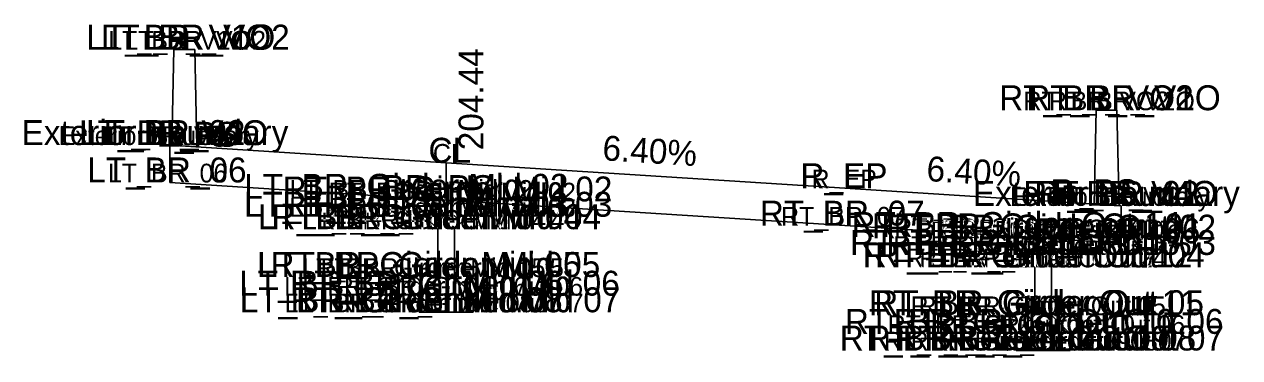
# Model space of a CAD drawing. Extents: x 1977765 to 1980293, y 795569 to 815181.
# Drawn here: x 1978023.5 to 1978072.25, y 807115.23 to 807128.6 of the extents above; entities that cross this region are included whole.
import ezdxf

# ---------------------------------------------------------------- set-up
doc = ezdxf.new("R2010")
doc.units = 0
for name, color, linetype in [('RD_Sketch5', 7, 'Continuous'), ('RD_XS_NewRW', 7, 'Continuous'), ('RD_XS_PaveOvlay', 7, 'Continuous'), ('RD_XS_TX_Elev_PR', 7, 'Continuous'), ('RD_XS_TX_Slope', 7, 'Continuous')]:
    doc.layers.add(name, color=color, linetype=linetype)

msp = doc.modelspace()

# ---------------------------------------------------------------- linework, layer by layer
at = {"layer": 'RD_XS_PaveOvlay'}
for points in [[(1978030.416, 807123.692), (1978030.332, 807127.589), (1978029.499, 807127.589), (1978029.416, 807123.756)], [(1978030.416, 807123.692), (1978030.332, 807127.589), (1978029.499, 807127.589), (1978029.416, 807123.756)], [(1978066.416, 807121.388), (1978066.499, 807125.157), (1978067.332, 807125.157), (1978067.416, 807121.324)], [(1978066.416, 807121.388), (1978066.499, 807125.157), (1978067.332, 807125.157), (1978067.416, 807121.324)], [(1978040.416, 807123.052), (1978029.332, 807123.761)], [(1978029.332, 807123.761), (1978029.332, 807122.261)], [(1978040.416, 807123.052), (1978029.332, 807123.761)], [(1978029.332, 807123.761), (1978029.332, 807122.261)], [(1978029.416, 807123.756), (1978030.416, 807123.692)], [(1978029.416, 807123.756), (1978030.416, 807123.692)], [(1978040.416, 807121.552), (1978040.416, 807123.052)], [(1978040.416, 807123.052), (1978056.416, 807122.028), (1978067.499, 807121.318)], [(1978040.416, 807121.552), (1978040.416, 807123.052)], [(1978040.416, 807121.552), (1978040.416, 807123.052)], [(1978040.416, 807123.052), (1978056.416, 807122.028), (1978067.499, 807121.318)], [(1978040.416, 807121.552), (1978040.416, 807123.052)], [(1978029.332, 807122.261), (1978040.416, 807121.552)], [(1978029.332, 807122.261), (1978040.416, 807121.552)], [(1978040.416, 807121.552), (1978039.582, 807121.605)], [(1978039.582, 807121.605), (1978039.582, 807120.885)], [(1978040.416, 807121.552), (1978039.582, 807121.605)], [(1978039.582, 807121.605), (1978039.582, 807120.885)], [(1978040.416, 807121.552), (1978041.249, 807121.498)], [(1978067.499, 807119.818), (1978056.416, 807120.528), (1978040.416, 807121.552)], [(1978040.416, 807121.552), (1978041.249, 807121.498)], [(1978067.499, 807119.818), (1978056.416, 807120.528), (1978040.416, 807121.552)], [(1978041.249, 807121.498), (1978041.249, 807120.885)], [(1978041.249, 807121.498), (1978041.249, 807120.885)], [(1978067.416, 807121.324), (1978066.416, 807121.388)], [(1978067.416, 807121.324), (1978066.416, 807121.388)], [(1978067.499, 807121.318), (1978067.499, 807119.818)], [(1978067.499, 807121.318), (1978067.499, 807119.818)], [(1978039.582, 807120.885), (1978040.082, 807120.385)], [(1978039.582, 807120.885), (1978040.082, 807120.385)], [(1978041.249, 807120.885), (1978040.749, 807120.385)], [(1978041.249, 807120.885), (1978040.749, 807120.385)], [(1978040.082, 807120.385), (1978040.082, 807118.468)], [(1978040.082, 807120.385), (1978040.082, 807118.468)], [(1978040.749, 807120.385), (1978040.749, 807118.468)], [(1978040.749, 807120.385), (1978040.749, 807118.468)], [(1978063.541, 807120.072), (1978064.374, 807120.018), (1978065.207, 807119.965)], [(1978063.541, 807119.352), (1978063.541, 807120.072)], [(1978063.541, 807120.072), (1978064.374, 807120.018), (1978065.207, 807119.965)], [(1978063.541, 807119.352), (1978063.541, 807120.072)], [(1978065.207, 807119.965), (1978065.207, 807119.352)], [(1978065.207, 807119.965), (1978065.207, 807119.352)], [(1978064.041, 807118.852), (1978063.541, 807119.352)], [(1978064.041, 807118.852), (1978063.541, 807119.352)], [(1978065.207, 807119.352), (1978064.707, 807118.852)], [(1978065.207, 807119.352), (1978064.707, 807118.852)], [(1978064.041, 807116.935), (1978064.041, 807118.852)], [(1978064.041, 807116.935), (1978064.041, 807118.852)], [(1978064.707, 807118.852), (1978064.707, 807116.935)], [(1978064.707, 807118.852), (1978064.707, 807116.935)], [(1978040.082, 807118.468), (1978039.332, 807117.718)], [(1978040.082, 807118.468), (1978039.332, 807117.718)], [(1978040.749, 807118.468), (1978041.499, 807117.718)], [(1978040.749, 807118.468), (1978041.499, 807117.718)], [(1978039.332, 807117.718), (1978039.332, 807117.052)], [(1978039.332, 807117.718), (1978039.332, 807117.052)], [(1978041.499, 807117.718), (1978041.499, 807117.052)], [(1978041.499, 807117.718), (1978041.499, 807117.052)], [(1978039.332, 807117.052), (1978040.416, 807117.052)], [(1978039.332, 807117.052), (1978040.416, 807117.052)], [(1978041.499, 807117.052), (1978040.416, 807117.052)], [(1978041.499, 807117.052), (1978040.416, 807117.052)], [(1978063.291, 807116.185), (1978064.041, 807116.935)], [(1978063.291, 807116.185), (1978064.041, 807116.935)], [(1978064.707, 807116.935), (1978065.457, 807116.185)], [(1978064.707, 807116.935), (1978065.457, 807116.185)], [(1978063.291, 807115.518), (1978063.291, 807116.185)], [(1978063.291, 807115.518), (1978063.291, 807116.185)], [(1978065.457, 807116.185), (1978065.457, 807115.518)], [(1978065.457, 807116.185), (1978065.457, 807115.518)], [(1978065.457, 807115.518), (1978064.374, 807115.518), (1978063.291, 807115.518)], [(1978065.457, 807115.518), (1978064.374, 807115.518), (1978063.291, 807115.518)]]:
    msp.add_lwpolyline(points, dxfattribs=at)

# ---------------------------------------------------------------- texts
at = {"layer": 'RD_Sketch5'}
for s, p in [('LT_BR_V1O', (1978025.983, 807127.589)), ('LT_BR_VO2', (1978026.565, 807127.589)), ('RT_BR_VO2', (1978062.605, 807125.157)), ('RT_BR_V1O', (1978063.691, 807125.157)), ('Exterior Boundary', (1978023.388, 807123.761)), ('LT_BR_V4O', (1978025.695, 807123.756)), ('LT_BR_02', (1978025.974, 807123.761)), ('L_PS', (1978028.798, 807123.692)), ('CL', (1978039.711, 807123.052)), ('LT_BR_06', (1978026.021, 807122.261)), ('R_EP', (1978054.632, 807122.028)), ('LT_BR_Girder Mid 02', (1978032.319, 807121.605)), ('RT_BR_Girder Mid 02', (1978033.859, 807121.498)), ('BR_PGL', (1978037.876, 807121.552)), ('R_PS', (1978064.672, 807121.388)), ('LT_BR_Girder Mid 03', (1978032.311, 807120.885)), ('RT_BR_Girder Mid 03', (1978033.851, 807120.885)), ('Exterior Boundary', (1978061.554, 807121.318)), ('RT_BR_V4O', (1978063.569, 807121.324)), ('RT_BR_02', (1978064.015, 807121.318)), ('LT_BR_Girder Mid 04', (1978032.866, 807120.385)), ('RT_BR_Girder Mid 04', (1978033.407, 807120.385)), ('RT_BR_07', (1978053.002, 807120.528)), ('RT_BR_Girder Out 14', (1978056.679, 807120.072)), ('RT_BR_Girder Out 01', (1978057.496, 807120.018)), ('RT_BR_Girder Out 02', (1978058.078, 807119.965)), ('RT_BR_06', (1978064.062, 807119.818)), ('RT_BR_Girder Out 13', (1978056.623, 807119.352)), ('RT_BR_Girder Out 03', (1978058.07, 807119.352)), ('LT_BR_Girder Mid 05', (1978032.834, 807118.468)), ('RT_BR_Girder Mid 05', (1978033.375, 807118.468)), ('RT_BR_Girder Out 12', (1978057.131, 807118.852)), ('RT_BR_Girder Out 04', (1978057.625, 807118.852)), ('LT_BR_Girder Mid 06', (1978032.116, 807117.718)), ('RT_BR_Girder Mid 06', (1978034.157, 807117.718)), ('LT_BR_Girder Mid 07', (1978032.14, 807117.052)), ('RT_BR_Girder Mid 07', (1978034.18, 807117.052)), ('BR_Girder Mid 08', (1978034.392, 807117.052)), ('RT_BR_Girder Out 11', (1978057.383, 807116.935)), ('RT_BR_Girder Out 05', (1978057.593, 807116.935)), ('RT_BR_Girder Out 10', (1978056.413, 807116.185)), ('RT_BR_Girder Out 06', (1978058.375, 807116.185)), ('RT_BR_Girder Out 09', (1978056.208, 807115.518)), ('RT_BR_Girder Out 08', (1978057.28, 807115.518)), ('RT_BR_Girder Out 07', (1978058.398, 807115.518))]:
    msp.add_text(s, height=1, dxfattribs=at).set_placement(p)
at = {"layer": 'RD_XS_NewRW'}
for s, p in [('LT_BR_V1O', (1978026.862, 807127.589)), ('LT_BR_VO2', (1978027.507, 807127.589)), ('RT_BR_VO2', (1978063.579, 807125.157)), ('RT_BR_V1O', (1978064.601, 807125.157)), ('Exterior Boundary', (1978024.874, 807123.761)), ('LT_BR_V4O', (1978026.625, 807123.756)), ('LT_BR_02', (1978026.814, 807123.761)), ('L_PS', (1978029.202, 807123.692)), ('CL', (1978039.887, 807123.052)), ('LT_BR_06', (1978026.849, 807122.261)), ('LT_BR_Girder Mid 02', (1978034.135, 807121.605)), ('R_EP', (1978055.078, 807122.028)), ('RT_BR_Girder Mid 02', (1978035.707, 807121.498)), ('BR_PGL', (1978038.511, 807121.552)), ('Exterior Boundary', (1978063.04, 807121.318)), ('RT_BR_V4O', (1978064.531, 807121.324)), ('RT_BR_02', (1978064.886, 807121.318)), ('R_PS', (1978065.108, 807121.388)), ('LT_BR_Girder Mid 03', (1978034.129, 807120.885)), ('RT_BR_Girder Mid 03', (1978035.701, 807120.885)), ('LT_BR_Girder Mid 04', (1978034.67, 807120.385)), ('RT_BR_Girder Mid 04', (1978035.242, 807120.385)), ('RT_BR_07', (1978053.856, 807120.528)), ('RT_BR_Girder Out 14', (1978058.394, 807120.072)), ('RT_BR_Girder Out 01', (1978059.216, 807120.018)), ('RT_BR_Girder Out 02', (1978059.86, 807119.965)), ('RT_BR_06', (1978064.921, 807119.818)), ('RT_BR_Girder Out 13', (1978058.353, 807119.352)), ('RT_BR_Girder Out 03', (1978059.854, 807119.352)), ('RT_BR_Girder Out 12', (1978058.859, 807118.852)), ('RT_BR_Girder Out 04', (1978059.395, 807118.852)), ('LT_BR_Girder Mid 05', (1978034.646, 807118.468)), ('RT_BR_Girder Mid 05', (1978035.219, 807118.468)), ('LT_BR_Girder Mid 06', (1978033.92, 807117.718)), ('RT_BR_Girder Mid 06', (1978035.992, 807117.718)), ('LT_BR_Girder Mid 07', (1978033.938, 807117.052)), ('BR_Girder Mid 08', (1978035.898, 807117.052)), ('RT_BR_Girder Mid 07', (1978036.01, 807117.052)), ('RT_BR_Girder Out 11', (1978059.048, 807116.935)), ('RT_BR_Girder Out 05', (1978059.372, 807116.935)), ('RT_BR_Girder Out 10', (1978058.132, 807116.185)), ('RT_BR_Girder Out 06', (1978060.145, 807116.185)), ('RT_BR_Girder Out 09', (1978057.979, 807115.518)), ('RT_BR_Girder Out 08', (1978059.053, 807115.518)), ('RT_BR_Girder Out 07', (1978060.163, 807115.518))]:
    msp.add_text(s, height=0.75, dxfattribs=at).set_placement(p)
at = {"layer": 'RD_XS_TX_Elev_PR'}
msp.add_text('204.44', height=1, rotation=90, dxfattribs=at).set_placement((1978041.916, 807123.552))
at = {"layer": 'RD_XS_TX_Slope'}
for p in [(1978046.668, 807123.153), (1978059.668, 807122.321)]:
    msp.add_text('6.40%', height=1, rotation=356.3381, dxfattribs=at).set_placement(p)

doc.saveas('drawing.dxf')
